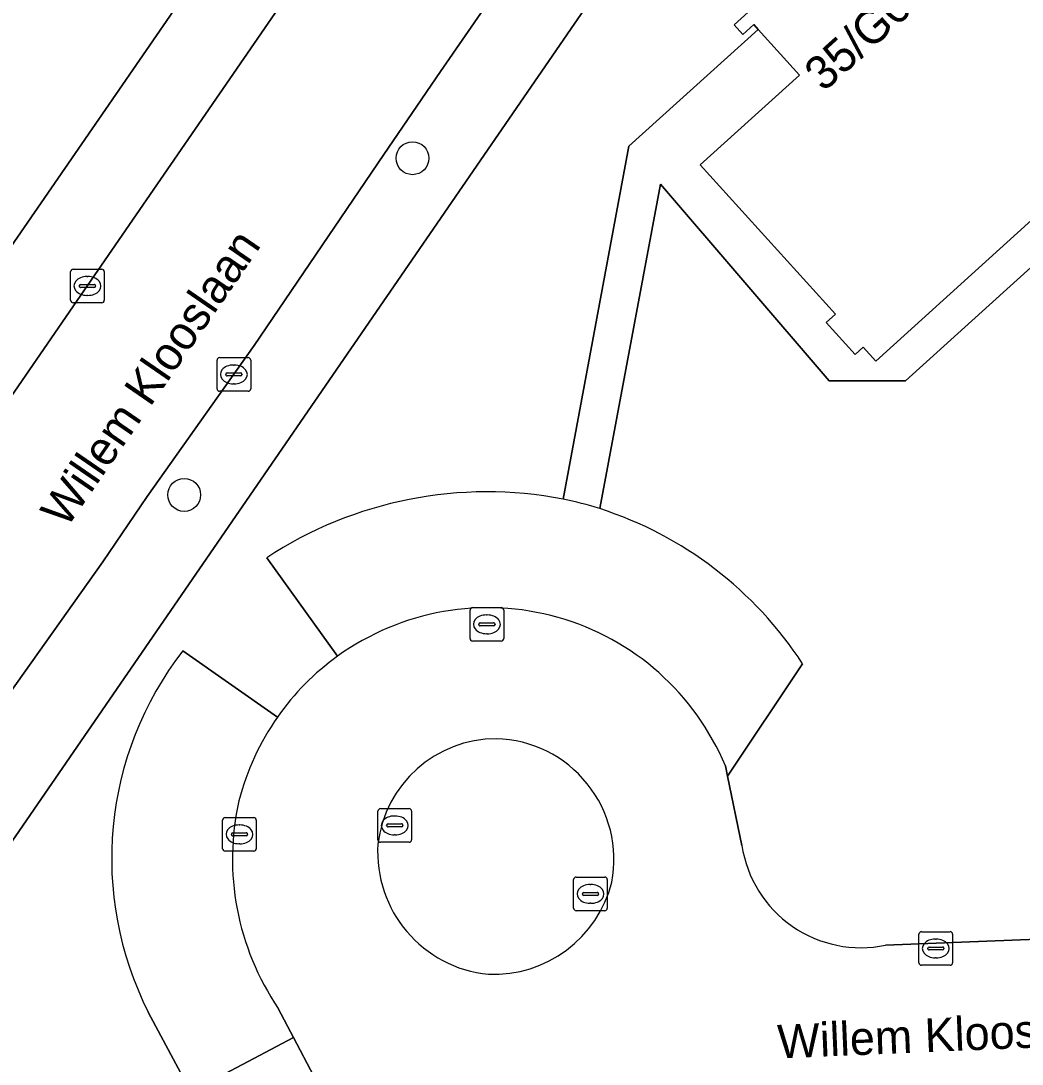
# Model space of a CAD drawing. Extents: x 160349 to 161355, y 381727 to 382854.
# Drawn here: x 160860.69 to 160890.48, y 382013.3 to 382044.33 of the extents above; entities that cross this region are included whole.
import ezdxf

# ---------------------------------------------------------------- set-up
doc = ezdxf.new("R2010")
doc.units = 0
for name, color, linetype in [('IMGEO_Boom', 7, 'Continuous'), ('IMGEO_Erf', 7, 'Continuous'), ('IMGEO_Groenvoorziening', 7, 'Continuous'), ('IMGEO_Kolk', 7, 'Continuous'), ('IMGEO_Openbare_ruimte_label', 7, 'Continuous'), ('IMGEO_Pand', 7, 'Continuous'), ('IMGEO_Pand_nummerreeks', 7, 'Continuous'), ('IMGEO_Parkeervlak_open', 7, 'Continuous'), ('IMGEO_Rijbaan_lokaal_open', 7, 'Continuous'), ('IMGEO_Voetpad_halfverhard', 7, 'Continuous'), ('IMGEO_Voetpad_open', 7, 'Continuous')]:
    doc.layers.add(name, color=color, linetype=linetype)

msp = doc.modelspace()

# ---------------------------------------------------------------- linework, layer by layer
at = {"layer": 'IMGEO_Boom'}
for centre in [(160872.339, 382040.248), (160865.548, 382030.233)]:
    msp.add_circle(centre, 0.489, dxfattribs=at)
at = {"layer": 'IMGEO_Erf'}
msp.add_lwpolyline([(160804.86, 381957.022), (160809.509, 381963.746), (160815.556, 381972.499), (160830.024, 381993.552), (160843.658, 382013.325), (160856.447, 382031.904), (160864.216, 382043.168), (160877.531, 382062.485), (160882.102, 382069.151)], dxfattribs=at)
at = {"layer": 'IMGEO_Groenvoorziening'}
for points in [[(160876.819, 382030.108), (160878.78, 382040.608), (160882.622, 382044.08), (160882.494, 382044.222), (160882.171, 382043.93), (160881.914, 382044.215), (160882.326, 382044.588), (160879.4, 382047.514), (160856.025, 382013.549), (160862.42, 382009.21), (160864.718, 382006.576), (160868.779, 382010.311), (160869.404, 382012.942), (160868.801, 382014.089), (160865.741, 382012.48), (160864.478, 382014.847)], [(160892.401, 382038.504), (160887.008, 382033.627), (160884.735, 382033.627), (160879.714, 382039.472), (160877.912, 382029.825)], [(160870.112, 382025.436), (160868.002, 382028.365)], [(160865.509, 382025.598), (160868.321, 382023.624)], [(160883.945, 382025.211), (160881.712, 382021.865), (160882.14, 382019.803)], [(160886.414, 382016.842), (160912.804, 382017.876)]]:
    msp.add_lwpolyline(points, dxfattribs=at)
for centre, radius, start, end in [((160874.552, 382018.402), 11.923, 79.041, 123.3238), ((160874.425, 382019.014), 11.359, 33.0604, 72.1225), ((160873.481, 382019.409), 10.092, 142.1731, 206.8713), ((160874.601, 382019.208), 7.678, 125.7831, 144.8848), ((160885.674, 382020.339), 3.574, 188.621, 281.9511)]:
    msp.add_arc(centre, radius, start, end, dxfattribs=at)
at = {"layer": 'IMGEO_Kolk'}
for p, q in [((160862.167, 382036.022), (160862.167, 382036.874)), ((160862.242, 382036.948), (160863.094, 382036.948)), ((160862.655, 382036.728), (160862.68, 382036.728)), ((160863.168, 382036.874), (160863.168, 382036.022)), ((160862.426, 382036.442), (160862.426, 382036.454)), ((160862.864, 382036.405), (160862.466, 382036.405)), ((160862.469, 382036.491), (160862.867, 382036.491)), ((160862.91, 382036.454), (160862.91, 382036.442)), ((160862.678, 382036.168), (160862.653, 382036.168)), ((160863.094, 382035.948), (160862.242, 382035.948)), ((160866.524, 382033.391), (160866.524, 382034.243)), ((160866.599, 382034.317), (160867.451, 382034.317)), ((160867.525, 382034.243), (160867.525, 382033.391)), ((160867.012, 382034.097), (160867.037, 382034.097)), ((160866.783, 382033.811), (160866.783, 382033.823)), ((160867.221, 382033.774), (160866.823, 382033.774)), ((160866.826, 382033.86), (160867.224, 382033.86)), ((160867.267, 382033.823), (160867.267, 382033.811)), ((160867.451, 382033.317), (160866.599, 382033.317)), ((160867.035, 382033.537), (160867.01, 382033.537)), ((160874.053, 382025.957), (160874.053, 382026.809)), ((160874.128, 382026.883), (160874.98, 382026.883)), ((160875.054, 382026.809), (160875.054, 382025.957)), ((160874.541, 382026.663), (160874.566, 382026.663)), ((160874.312, 382026.377), (160874.312, 382026.389)), ((160874.75, 382026.34), (160874.352, 382026.34)), ((160874.355, 382026.426), (160874.753, 382026.426)), ((160874.796, 382026.389), (160874.796, 382026.377)), ((160874.98, 382025.883), (160874.128, 382025.883)), ((160874.564, 382026.103), (160874.539, 382026.103)), ((160871.387, 382020.902), (160872.239, 382020.902)), ((160866.691, 382019.71), (160866.691, 382020.562)), ((160866.766, 382020.636), (160867.618, 382020.636)), ((160867.692, 382020.562), (160867.692, 382019.71)), ((160871.312, 382019.976), (160871.312, 382020.828)), ((160871.8, 382020.682), (160871.825, 382020.682)), ((160872.313, 382020.828), (160872.313, 382019.976)), ((160867.179, 382020.416), (160867.204, 382020.416)), ((160871.571, 382020.396), (160871.571, 382020.408)), ((160872.009, 382020.359), (160871.611, 382020.359)), ((160871.614, 382020.445), (160872.012, 382020.445)), ((160872.055, 382020.408), (160872.055, 382020.396)), ((160866.95, 382020.13), (160866.95, 382020.142)), ((160867.388, 382020.093), (160866.99, 382020.093)), ((160866.993, 382020.179), (160867.391, 382020.179)), ((160867.434, 382020.142), (160867.434, 382020.13)), ((160871.823, 382020.122), (160871.798, 382020.122)), ((160867.618, 382019.636), (160866.766, 382019.636)), ((160867.202, 382019.856), (160867.177, 382019.856)), ((160872.239, 382019.902), (160871.387, 382019.902)), ((160877.134, 382017.938), (160877.134, 382018.79)), ((160877.209, 382018.864), (160878.061, 382018.864)), ((160878.135, 382018.79), (160878.135, 382017.938)), ((160877.436, 382018.407), (160877.834, 382018.407)), ((160877.622, 382018.644), (160877.647, 382018.644)), ((160877.393, 382018.358), (160877.393, 382018.37)), ((160877.831, 382018.321), (160877.433, 382018.321)), ((160877.645, 382018.084), (160877.62, 382018.084)), ((160877.877, 382018.37), (160877.877, 382018.358)), ((160878.061, 382017.864), (160877.209, 382017.864)), ((160887.408, 382016.315), (160887.408, 382017.167)), ((160887.483, 382017.241), (160888.335, 382017.241)), ((160888.409, 382017.167), (160888.409, 382016.315)), ((160887.896, 382017.021), (160887.921, 382017.021)), ((160887.667, 382016.735), (160887.667, 382016.747)), ((160888.105, 382016.698), (160887.707, 382016.698)), ((160887.71, 382016.784), (160888.108, 382016.784)), ((160888.151, 382016.747), (160888.151, 382016.735)), ((160888.335, 382016.241), (160887.483, 382016.241)), ((160887.919, 382016.461), (160887.894, 382016.461))]:
    msp.add_line(p, q, dxfattribs=at)
for points in [[(160862.167, 382036.022), (160862.167, 382036.874)], [(160862.242, 382036.948), (160863.094, 382036.948)], [(160863.168, 382036.874), (160863.168, 382036.022)], [(160863.094, 382035.948), (160862.242, 382035.948)], [(160866.524, 382033.391), (160866.524, 382034.243)], [(160866.599, 382034.317), (160867.451, 382034.317)], [(160867.525, 382034.243), (160867.525, 382033.391)], [(160867.451, 382033.317), (160866.599, 382033.317)], [(160874.053, 382025.957), (160874.053, 382026.809)], [(160874.128, 382026.883), (160874.98, 382026.883)], [(160875.054, 382026.809), (160875.054, 382025.957)], [(160874.98, 382025.883), (160874.128, 382025.883)], [(160871.387, 382020.902), (160872.239, 382020.902)], [(160866.691, 382019.71), (160866.691, 382020.562)], [(160866.766, 382020.636), (160867.618, 382020.636)], [(160867.692, 382020.562), (160867.692, 382019.71)], [(160871.312, 382019.976), (160871.312, 382020.828)], [(160872.313, 382020.828), (160872.313, 382019.976)], [(160867.618, 382019.636), (160866.766, 382019.636)], [(160872.239, 382019.902), (160871.387, 382019.902)], [(160877.134, 382017.938), (160877.134, 382018.79)], [(160877.209, 382018.864), (160878.061, 382018.864)], [(160878.135, 382018.79), (160878.135, 382017.938)], [(160878.061, 382017.864), (160877.209, 382017.864)], [(160887.408, 382016.315), (160887.408, 382017.167)], [(160887.483, 382017.241), (160888.335, 382017.241)], [(160888.409, 382017.167), (160888.409, 382016.315)], [(160888.335, 382016.241), (160887.483, 382016.241)]]:
    msp.add_lwpolyline(points, dxfattribs=at)
for centre, radius, start, end in [((160862.244, 382036.872), 0.0765, 91.552, 178.448), ((160862.244, 382036.872), 0.0765, 91.552, 178.448), ((160863.092, 382036.872), 0.0765, 1.552, 88.448), ((160863.092, 382036.872), 0.0765, 1.552, 88.448), ((160862.466, 382036.451), 0.0403, 85.8775, 175.7526), ((160862.463, 382036.441), 0.0366, 178.938, 274.7102), ((160862.867, 382036.448), 0.043, 264.8664, 352.4533), ((160862.871, 382036.453), 0.0386, 1.7309, 96.639), ((160862.244, 382036.024), 0.0765, 181.552, 268.448), ((160862.244, 382036.024), 0.0765, 181.552, 268.448), ((160863.092, 382036.024), 0.0765, 271.552, 358.448), ((160863.092, 382036.024), 0.0765, 271.552, 358.448), ((160866.601, 382034.241), 0.0765, 91.552, 178.448), ((160866.601, 382034.241), 0.0765, 91.552, 178.448), ((160867.449, 382034.241), 0.0765, 1.552, 88.448), ((160867.449, 382034.241), 0.0765, 1.552, 88.448), ((160866.823, 382033.82), 0.0403, 85.8775, 175.7526), ((160866.82, 382033.81), 0.0366, 178.938, 274.7102), ((160867.224, 382033.817), 0.043, 264.8664, 352.4533), ((160867.228, 382033.822), 0.0386, 1.7309, 96.639), ((160866.601, 382033.393), 0.0765, 181.552, 268.448), ((160866.601, 382033.393), 0.0765, 181.552, 268.448), ((160867.449, 382033.393), 0.0765, 271.552, 358.448), ((160867.449, 382033.393), 0.0765, 271.552, 358.448), ((160874.13, 382026.807), 0.0765, 91.552, 178.448), ((160874.13, 382026.807), 0.0765, 91.552, 178.448), ((160874.978, 382026.807), 0.0765, 1.552, 88.448), ((160874.978, 382026.807), 0.0765, 1.552, 88.448), ((160874.352, 382026.386), 0.0403, 85.8775, 175.7526), ((160874.349, 382026.376), 0.0366, 178.938, 274.7102), ((160874.753, 382026.383), 0.043, 264.8664, 352.4533), ((160874.757, 382026.388), 0.0386, 1.7309, 96.639), ((160874.13, 382025.959), 0.0765, 181.552, 268.448), ((160874.13, 382025.959), 0.0765, 181.552, 268.448), ((160874.978, 382025.959), 0.0765, 271.552, 358.448), ((160874.978, 382025.959), 0.0765, 271.552, 358.448), ((160871.389, 382020.826), 0.0765, 91.552, 178.448), ((160871.389, 382020.826), 0.0765, 91.552, 178.448), ((160872.237, 382020.826), 0.0765, 1.552, 88.448), ((160872.237, 382020.826), 0.0765, 1.552, 88.448), ((160866.768, 382020.56), 0.0765, 91.552, 178.448), ((160866.768, 382020.56), 0.0765, 91.552, 178.448), ((160867.616, 382020.56), 0.0765, 1.552, 88.448), ((160867.616, 382020.56), 0.0765, 1.552, 88.448), ((160871.611, 382020.405), 0.0403, 85.8775, 175.7526), ((160871.608, 382020.395), 0.0366, 178.938, 274.7102), ((160872.012, 382020.402), 0.043, 264.8664, 352.4533), ((160872.016, 382020.407), 0.0386, 1.7309, 96.639), ((160866.99, 382020.139), 0.0403, 85.8775, 175.7526), ((160866.987, 382020.129), 0.0366, 178.938, 274.7102), ((160867.391, 382020.136), 0.043, 264.8664, 352.4533), ((160867.395, 382020.141), 0.0386, 1.7309, 96.639), ((160871.389, 382019.978), 0.0765, 181.552, 268.448), ((160871.389, 382019.978), 0.0765, 181.552, 268.448), ((160872.237, 382019.978), 0.0765, 271.552, 358.448), ((160872.237, 382019.978), 0.0765, 271.552, 358.448), ((160866.768, 382019.712), 0.0765, 181.552, 268.448), ((160866.768, 382019.712), 0.0765, 181.552, 268.448), ((160867.616, 382019.712), 0.0765, 271.552, 358.448), ((160867.616, 382019.712), 0.0765, 271.552, 358.448), ((160877.211, 382018.788), 0.0765, 91.552, 178.448), ((160877.211, 382018.788), 0.0765, 91.552, 178.448), ((160878.059, 382018.788), 0.0765, 1.552, 88.448), ((160878.059, 382018.788), 0.0765, 1.552, 88.448), ((160877.433, 382018.367), 0.0403, 85.8775, 175.7526), ((160877.838, 382018.369), 0.0386, 1.7309, 96.639), ((160877.43, 382018.357), 0.0366, 178.938, 274.7102), ((160877.834, 382018.364), 0.043, 264.8664, 352.4533), ((160877.211, 382017.94), 0.0765, 181.552, 268.448), ((160877.211, 382017.94), 0.0765, 181.552, 268.448), ((160878.059, 382017.94), 0.0765, 271.552, 358.448), ((160878.059, 382017.94), 0.0765, 271.552, 358.448), ((160887.485, 382017.165), 0.0765, 91.552, 178.448), ((160887.485, 382017.165), 0.0765, 91.552, 178.448), ((160888.333, 382017.165), 0.0765, 1.552, 88.448), ((160888.333, 382017.165), 0.0765, 1.552, 88.448), ((160887.707, 382016.744), 0.0403, 85.8775, 175.7526), ((160887.704, 382016.734), 0.0366, 178.938, 274.7102), ((160888.108, 382016.741), 0.043, 264.8664, 352.4533), ((160888.112, 382016.746), 0.0386, 1.7309, 96.639), ((160887.485, 382016.317), 0.0765, 181.552, 268.448), ((160887.485, 382016.317), 0.0765, 181.552, 268.448), ((160888.333, 382016.317), 0.0765, 271.552, 358.448), ((160888.333, 382016.317), 0.0765, 271.552, 358.448)]:
    msp.add_arc(centre, radius, start, end, dxfattribs=at)
for centre, major_axis, ratio, start_param, end_param in [((160862.654, 382036.448), (-0.387, 0.002), 0.722429, 4.712389, 7.853982), ((160862.679, 382036.448), (-0.39, 0.002), 0.717154, 1.570796, 4.712389), ((160867.011, 382033.817), (-0.387, 0.002), 0.722429, 4.712389, 7.853982), ((160867.036, 382033.817), (-0.39, 0.002), 0.717154, 1.570796, 4.712389), ((160874.54, 382026.383), (-0.387, 0.002), 0.722429, 4.712389, 7.853982), ((160874.565, 382026.383), (-0.39, 0.002), 0.717154, 1.570796, 4.712389), ((160871.799, 382020.402), (-0.387, 0.002), 0.722429, 4.712389, 7.853982), ((160871.824, 382020.402), (-0.39, 0.002), 0.717154, 1.570796, 4.712389), ((160867.178, 382020.136), (-0.387, 0.002), 0.722429, 4.712389, 7.853982), ((160867.203, 382020.136), (-0.39, 0.002), 0.717154, 1.570796, 4.712389), ((160877.621, 382018.364), (-0.387, 0.002), 0.722429, 4.712389, 7.853982), ((160877.646, 382018.364), (-0.39, 0.002), 0.717154, 1.570796, 4.712389), ((160887.895, 382016.741), (-0.387, 0.002), 0.722429, 4.712389, 7.853982), ((160887.92, 382016.741), (-0.39, 0.002), 0.717154, 1.570796, 4.712389)]:
    msp.add_ellipse(centre, major_axis=major_axis, ratio=ratio, start_param=start_param, end_param=end_param, dxfattribs=at)
at = {"layer": 'IMGEO_Pand'}
msp.add_lwpolyline([(160896.165, 382043.298), (160894.271, 382045.393), (160889.299, 382050.892), (160882.326, 382044.588), (160881.914, 382044.215), (160882.171, 382043.93), (160882.494, 382044.222), (160882.622, 382044.08), (160883.852, 382042.719), (160880.903, 382040.052), (160884.923, 382035.606), (160884.648, 382035.358), (160885.507, 382034.408), (160885.749, 382034.627), (160886.12, 382034.216), (160892.87, 382040.319)], close=True, dxfattribs=at)
at = {"layer": 'IMGEO_Parkeervlak_open'}
for points in [[(160868.002, 382028.365), (160870.112, 382025.436)], [(160868.321, 382023.624), (160865.509, 382025.598)], [(160881.649, 382022.17), (160881.712, 382021.865), (160883.945, 382025.211)], [(160864.478, 382014.847), (160865.741, 382012.48), (160868.801, 382014.089), (160868.345, 382014.956)]]:
    msp.add_lwpolyline(points, dxfattribs=at)
for centre, radius, start, end in [((160874.552, 382018.402), 11.923, 79.041, 123.3238), ((160874.657, 382019.505), 10.821, 72.4934, 78.4741), ((160874.425, 382019.014), 11.359, 33.0604, 72.1225), ((160874.584, 382019.224), 7.654, 22.6353, 125.7522), ((160873.481, 382019.409), 10.092, 142.1731, 206.8713), ((160874.734, 382019.156), 7.816, 145.1356, 165.3258), ((160874.946, 382019.409), 7.963, 167.4748, 214.0018)]:
    msp.add_arc(centre, radius, start, end, dxfattribs=at)
at = {"layer": 'IMGEO_Rijbaan_lokaal_open'}
for points in [[(160900.454, 382091.336), (160898.732, 382088.827), (160897.579, 382087.17), (160888.911, 382074.534), (160875.487, 382055.069), (160862.667, 382036.458), (160849.849, 382017.829), (160838.733, 382001.705), (160827.599, 381985.555), (160816.487, 381969.406), (160806.996, 381955.65)], [(160863.124, 382028.242), (160864.448, 382030.182), (160867.631, 382034.676), (160871.484, 382040.355), (160873.174, 382042.828), (160877.127, 382048.557), (160882.027, 382055.784), (160885.092, 382060.107), (160889.498, 382066.61), (160894.202, 382073.493), (160902.442, 382085.568), (160903.558, 382087.228), (160905.012, 382089.324)], [(160811.585, 381953.706), (160812.427, 381954.838), (160843.491, 382000), (160849.506, 382008.744), (160855.258, 382017.034), (160858.854, 382022.23), (160863.124, 382028.242)]]:
    msp.add_lwpolyline(points, dxfattribs=at)
at = {"layer": 'IMGEO_Voetpad_halfverhard'}
for points in [[(160892.87, 382040.319), (160886.12, 382034.216), (160885.749, 382034.627), (160885.507, 382034.408), (160884.648, 382035.358), (160884.923, 382035.606), (160880.903, 382040.052), (160883.852, 382042.719), (160882.622, 382044.08), (160878.78, 382040.608), (160876.819, 382030.108)], [(160877.912, 382029.825), (160879.714, 382039.472), (160884.735, 382033.627), (160887.008, 382033.627), (160892.401, 382038.504)]]:
    msp.add_lwpolyline(points, dxfattribs=at)
msp.add_arc((160874.657, 382019.505), 10.821, 72.4934, 78.4741, dxfattribs=at)
at = {"layer": 'IMGEO_Voetpad_open'}
for points in [[(160898.701, 382093.297), (160896.288, 382089.767), (160892.908, 382084.909), (160891.222, 382082.372), (160890.681, 382081.588), (160886.418, 382075.41), (160884.468, 382072.583), (160883.88, 382071.73), (160882.102, 382069.151), (160877.531, 382062.485), (160864.216, 382043.168), (160856.447, 382031.904), (160843.658, 382013.325), (160830.024, 381993.552), (160815.556, 381972.499), (160809.509, 381963.746)], [(160905.012, 382089.324), (160903.558, 382087.228), (160902.442, 382085.568), (160894.202, 382073.493), (160889.498, 382066.61), (160885.092, 382060.107), (160882.027, 382055.784), (160877.127, 382048.557), (160873.174, 382042.828), (160871.484, 382040.355), (160867.631, 382034.676), (160864.448, 382030.182), (160863.124, 382028.242), (160858.854, 382022.23), (160855.258, 382017.034), (160849.506, 382008.744), (160843.491, 382000), (160812.427, 381954.838), (160811.585, 381953.706)], [(160816.487, 381969.406), (160827.599, 381985.555), (160838.733, 382001.705), (160849.849, 382017.829), (160862.667, 382036.458), (160875.487, 382055.069), (160888.911, 382074.534), (160897.579, 382087.17)], [(160815.016, 381954.084), (160820.18, 381961.222), (160821.136, 381962.535), (160825.506, 381968.975), (160826.232, 381970.197), (160846.705, 382000), (160849.898, 382004.648), (160850.803, 382005.961), (160855.241, 382012.41), (160856.025, 382013.549), (160879.4, 382047.514)], [(160882.14, 382019.803), (160881.712, 382021.865), (160881.649, 382022.17)], [(160912.804, 382017.876), (160886.414, 382016.842)], [(160868.345, 382014.956), (160868.801, 382014.089), (160869.404, 382012.942), (160868.779, 382010.311), (160864.718, 382006.576), (160862.42, 382009.21), (160856.025, 382013.549), (160855.241, 382012.41), (160859.749, 382009.38), (160854.038, 382004.118), (160850.803, 382005.961), (160849.898, 382004.648), (160851.989, 382003.226), (160853.684, 382001.636), (160860.869, 382007.993), (160865.703, 382002.529), (160872.511, 382008.553), (160877.378, 382003.052), (160884.155, 382009.049), (160889.052, 382003.514), (160895.757, 382009.447)]]:
    msp.add_lwpolyline(points, dxfattribs=at)
for centre, radius, start, end in [((160874.584, 382019.224), 7.654, 22.6353, 125.7522), ((160874.601, 382019.208), 7.678, 125.7831, 144.8848), ((160874.734, 382019.156), 7.816, 145.1356, 165.3258), ((160874.833, 382019.434), 3.546, 89.9753, 173.3382), ((160874.833, 382019.434), 3.546, 89.9753, 173.3382), ((160874.738, 382019.386), 3.596, 349.2183, 88.4509), ((160874.738, 382019.386), 3.596, 349.2183, 88.4509), ((160874.946, 382019.409), 7.963, 167.4748, 214.0018), ((160874.958, 382019.61), 3.655, 176.321, 264.3875), ((160874.958, 382019.61), 3.655, 176.321, 264.3875), ((160885.674, 382020.339), 3.574, 188.621, 281.9511), ((160874.745, 382019.607), 3.636, 267.7296, 345.775), ((160874.745, 382019.607), 3.636, 267.7296, 345.775)]:
    msp.add_arc(centre, radius, start, end, dxfattribs=at)

# ---------------------------------------------------------------- texts
at = {"layer": 'IMGEO_Openbare_ruimte_label'}
for rotation, p in [(55.4679, (160862.045, 382029.214)), (2.4647, (160883.219, 382013.467))]:
    msp.add_text('Willem Klooslaan', height=1, rotation=rotation, dxfattribs=at).set_placement(p)
at = {"layer": 'IMGEO_Pand_nummerreeks'}
msp.add_text('35/G01-41', height=1, rotation=42.1181, dxfattribs=at).set_placement((160884.574, 382042.198))

doc.saveas('drawing.dxf')
